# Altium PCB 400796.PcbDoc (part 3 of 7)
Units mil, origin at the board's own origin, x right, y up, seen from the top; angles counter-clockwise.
Board outline 2086.61 x 2086.61 mil, 6 copper layers (Top Layer, Mid Layer 1, Mid Layer 2, Mid Layer 3, Mid Layer 4, Bottom Layer), stack 58.818 mil thick; 313 components, 234 nets, 1244 pads, 2538 vias.
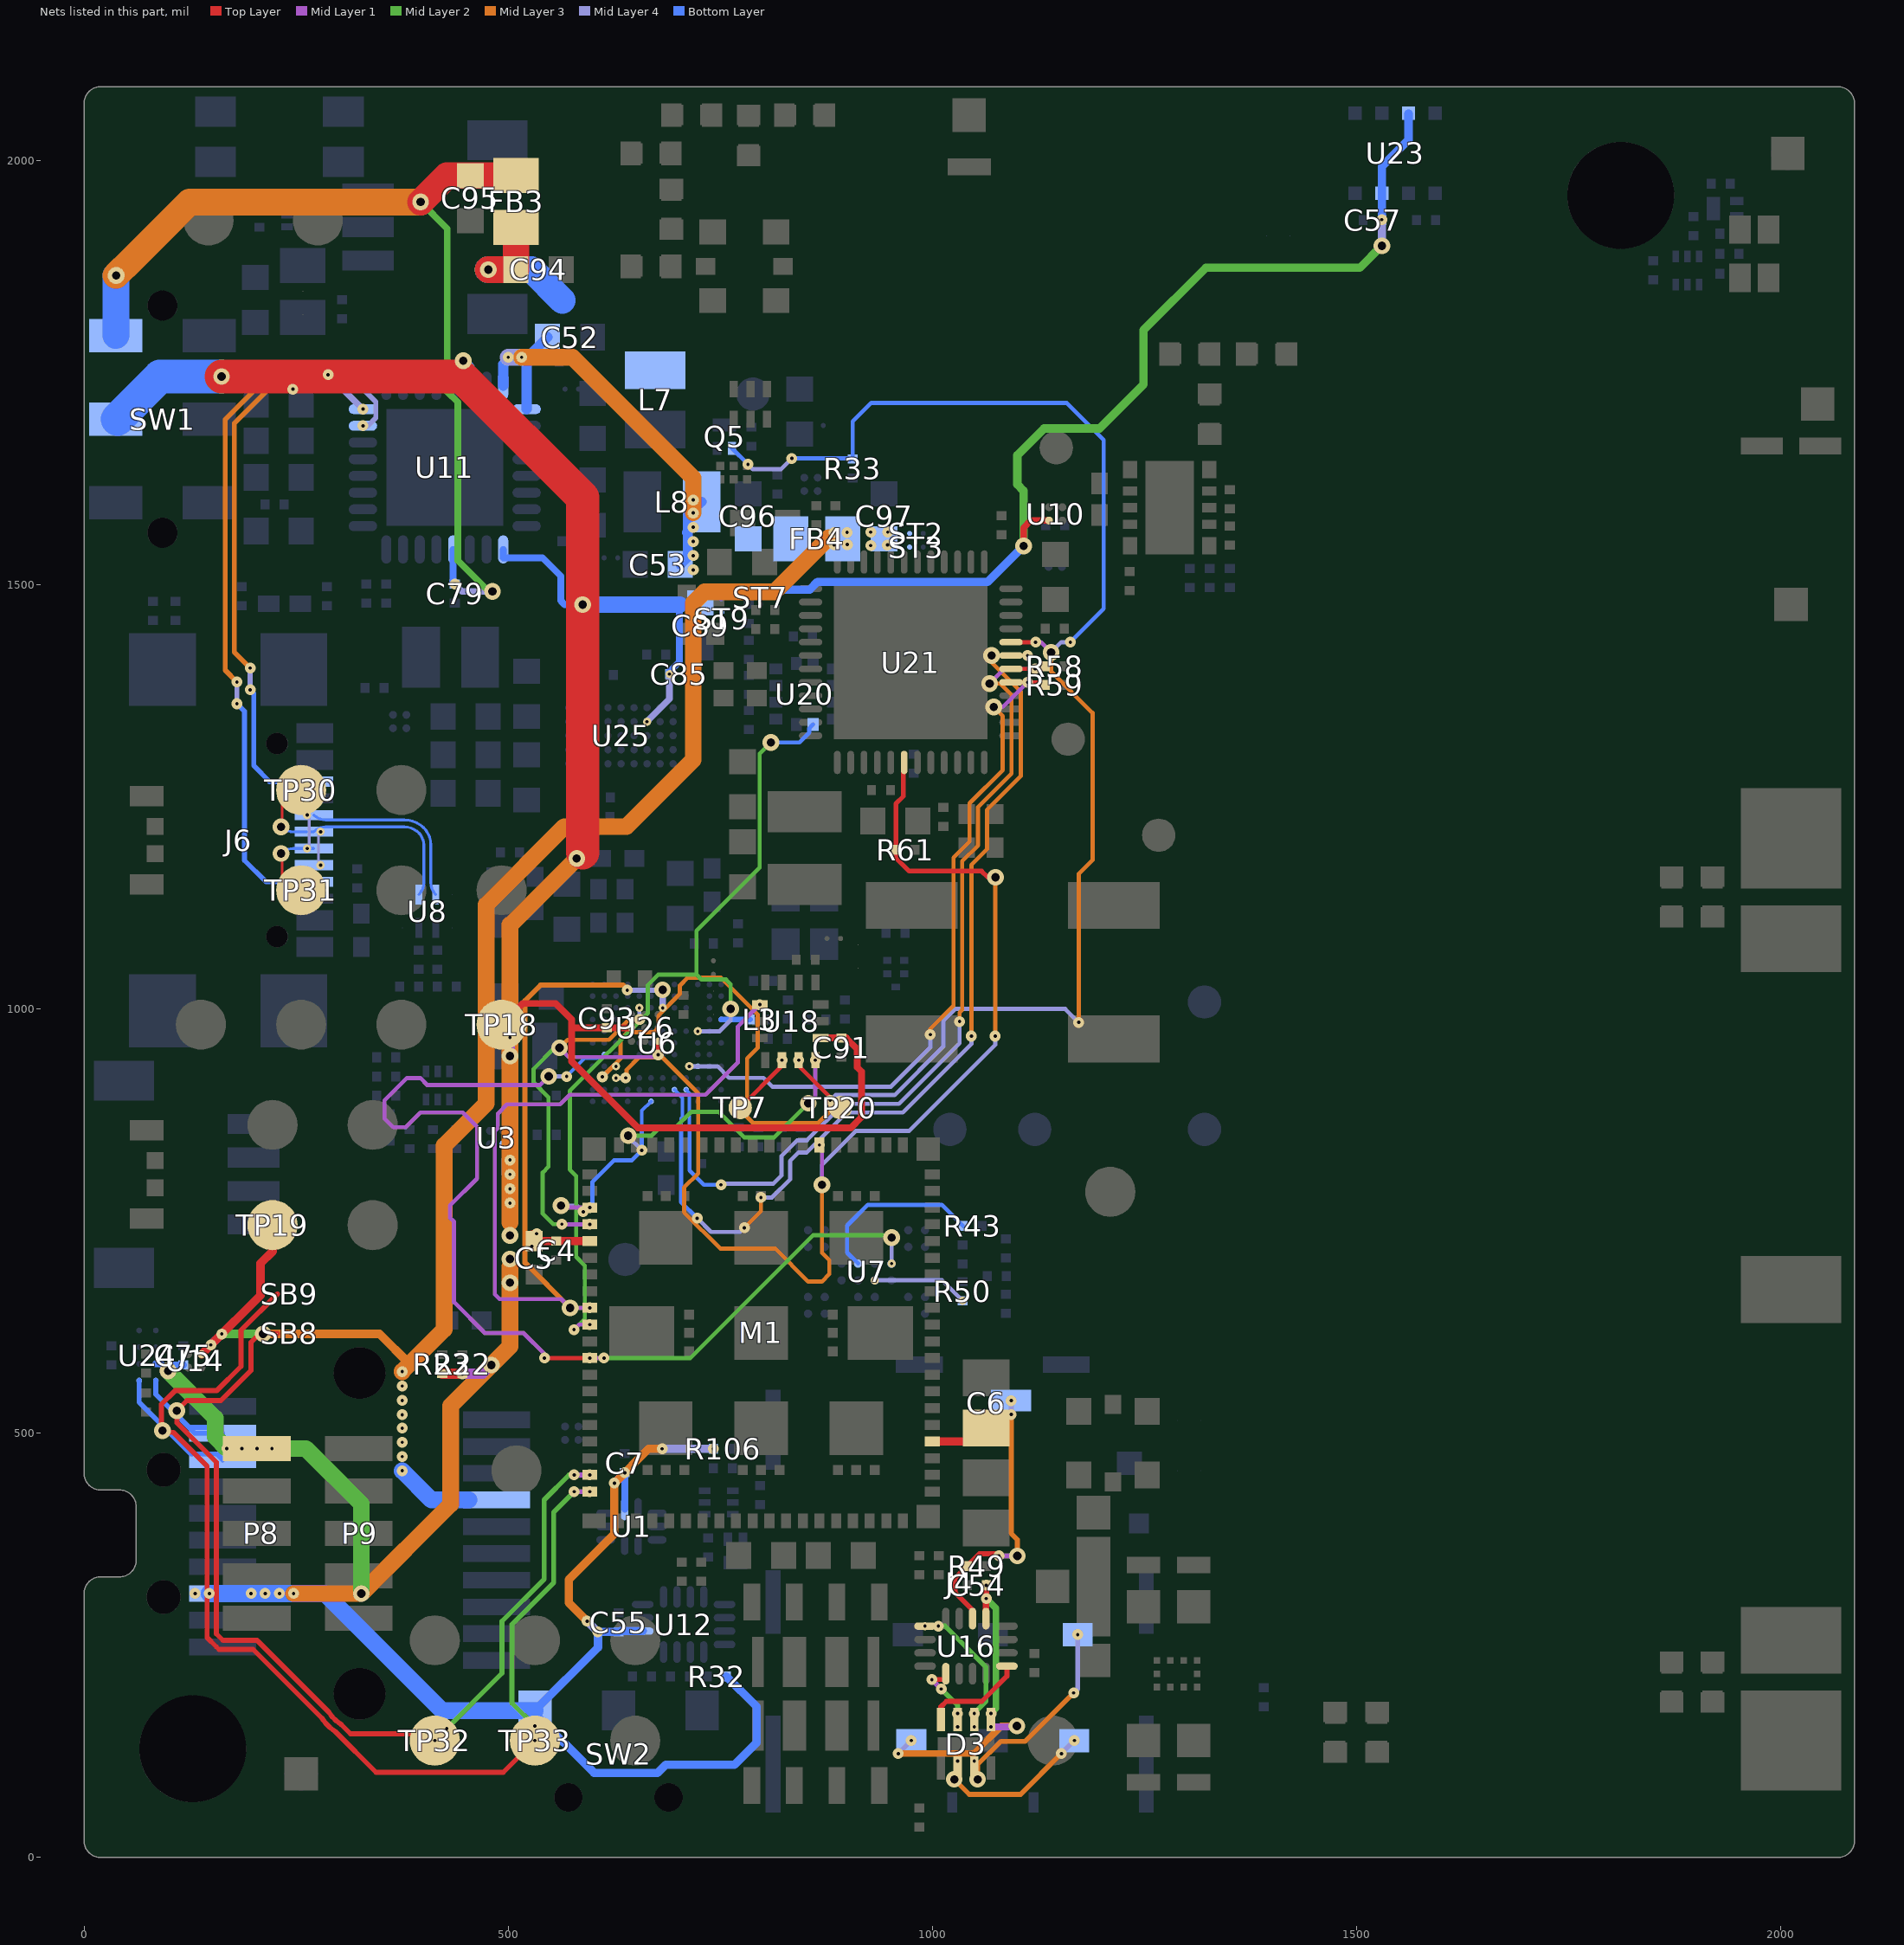
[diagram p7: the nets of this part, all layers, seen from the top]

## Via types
v1: diameter 12.8, hole 3.94, Mid Layer 4 to Bottom Layer, tented both sides, 653 vias
v2: diameter 12.8, hole 3.94, Top Layer to Mid Layer 1, tented both sides, 560 vias
v3: diameter 12.8, hole 3.94, Mid Layer 3 to Mid Layer 4, tented both sides, 388 vias
v4: diameter 19.68, hole 9.84, Mid Layer 1 to Mid Layer 4, tented both sides, 311 vias
v5: diameter 12.8, hole 3.94, Mid Layer 1 to Mid Layer 2, tented both sides, 265 vias
v6: diameter 19.68, hole 9.84, Top Layer to Bottom Layer, tented both sides, 169 vias
v7: diameter 9.84, hole 3.94, Mid Layer 4 to Bottom Layer, tented both sides, 105 vias
v8: diameter 12.8, hole 3.94, Top Layer to Mid Layer 1, tented top, 70 vias
v9: diameter 9.84, hole 3.94, Top Layer to Mid Layer 1, tented both sides, 17 vias

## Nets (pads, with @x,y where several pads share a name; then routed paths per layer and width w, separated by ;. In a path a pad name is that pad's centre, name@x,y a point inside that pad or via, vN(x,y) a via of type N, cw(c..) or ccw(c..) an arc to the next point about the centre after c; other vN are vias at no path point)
1V8: C79.1 C95.2 FB3.2 SW1.3 U11.12 | length 1176.4
  Top Layer w31.5: v6(396.65,1950.79) 427.79,1981.93 FB3.2@509.1,1981.93
  Mid Layer 2 w7.87: v6(396.65,1950.79) 428.15,1919.29 428.15,1727.2 440.63,1714.71 440.63,1528.2 476.88,1491.95 v4(481.32,1491.95)
  Mid Layer 3 w31.5: v6(37.8,1864.21) 56.6,1883 124.38,1950.79 v6(396.65,1950.79)
  Mid Layer 4 w7.87: v1(437.01,1500.39) 445.45,1491.95 v4(481.32,1491.95)
  Bottom Layer w7.87: C79.1@435.04,1500.39 U11.12@435.04,1541.34
  Bottom Layer w31.5: SW1.3@37.4,1793.31 37.8,1793.7 v6(37.8,1864.21)
1V8_IND: C52.2 C94.2 FB3.1 L7.1 U11.1 | length 279.9
  Top Layer w31.5: v6(476.38,1871.06) C94.2@509.1,1871.06 FB3.1@509.1,1920.9
  Bottom Layer w11.81: U11.1@521.65,1706.69 521.65,1766.89 C52.2@546.26,1791.5
  Bottom Layer w31.5: v6(476.38,1871.06) 527.56,1871.06 563.71,1834.92
1V8_SW: C4.1 C5.1 C7.1 C55.1 C57.2 C75.2 C85.1 C89.2 C91.2 C93.2 M1.65 P8.1 P9.3 R22.1 R23.1 R32.1 R106.1 ST7.1 ST9.1 SW1.2 SW2.3 TP18.1 U1.1 U3.A2 U10.A2 U11.9 U11.30 U12.14 U18.5 U23.2 U23.6 U24.C1 U25.C4 U26.B3 | length 6568.8
  Top Layer w7.87: v6(1107.28,1545.28) 1107.28,1566.95 1115.73,1575.39 U10.A2@1137.32,1575.39
  Top Layer w8: TP18.1@492.13,981.39 517.14,1006.4 555.8,1006.4 574.65,987.55 574.65,977.75 ; C5.1@527.54,735.1 v2(533.52,735.1) ; C5.1@530.62,726.38 C5.1@530.62,729.24 ; U26.B3@645.2,977.61 C93.2@616.14,977.61 574.79,977.61 574.65,977.75 ; U18.5@868.33,965.69 C91.2@892.87,965.69 898.4,965.69 911.14,952.95 911.14,931.27 916.27,926.15 916.27,872.24 903.87,859.84 652.83,859.84 574.65,938.02 574.65,977.75
  Top Layer w9.84: C5.1@530.62,726.38 M1.65@596.16,726.38
  Top Layer w12: R23.1@422.16,570.07 v2(445.78,570.07) ; TP18.1@492.13,981.39 501.95,971.56 v2(501.95,966.21)
  Top Layer w39.37: v6(162.13,1745.08) 444.88,1745.08 587.6,1602.36 v6(587.6,1476.38) v6@587.6,1184.05
  Mid Layer 1 w12: v2(445.78,570.07) 469.78,570.07 v4(480.05,580.34) ; v4(501.95,944.46) v2(501.95,966.21)
  Mid Layer 2 w9.84: v6(1107.28,1545.28) 1107.28,1610.53 1099.95,1617.87 1099.95,1652.43 1131.39,1683.87 1196.85,1683.87 1248.57,1735.59 1248.57,1799.65 1322.27,1873.35 1503.71,1873.35 v4(1529.53,1899.17)
  Mid Layer 2 w19.68: v6(99.15,573.25) 154.61,517.79 154.61,495.58 v5(168.31,481.89) v5(186.02,481.89) 261.65,481.89 326.77,416.77 v4(326.77,311.02)
  Mid Layer 3 w9.84: v3(592.97,278.54) 571.51,300 571.51,327.6 625.06,381.14 v3(625.06,441.2) 665.52,481.66 v3(681.37,481.66)
  Mid Layer 3 w19.68: v3(247.05,311.02) v4(326.77,311.02) 432.09,416.34 432.09,532.38 v4(480.05,580.34) 501.97,602.26 v4(501.97,677.25) v4@501.97,696.25 ; 501.95,748.03 501.95,1099.41 ; 502.95,1099.41 v6(580.71,1177.16)
  Mid Layer 4 w7.87: v7@663.58,1338.92 690.02,1365.36 v7(690.02,1394.5)
  Mid Layer 4 w9.84: v3(592.97,278.54) v1(605.76,265.75) ; v3(625.06,441.2) v1(637.25,453.39) ; v3(681.37,481.66) 681.45,481.59 v1(741.84,481.59) ; v4(1529.53,1899.17) v1(1529.53,1929.98)
  Bottom Layer w7.87: U11.9@494.09,1541.34 494.09,1531.5 540.35,1531.5 562.01,1509.84 562.01,1481.3 ; 562.4,1480.41 566.43,1476.38 v6(587.6,1476.38) ; v7(690.02,1394.5) 690.02,1397.7 701.77,1409.45 701.77,1476.38
  Bottom Layer w8: U24.C1@84.65,581.69 90.71,581.69 v6(99.15,573.25) 106.21,580.31 C75.2@117.13,580.31 ; U1.1@637.25,410.44 v1(637.25,453.39)
  Bottom Layer w9.84: C55.1@629.92,265.75 v1(605.76,265.75) 605.76,247.49 SW2.3@531.5,173.23 531.5,169.23 600.98,99.75 675.98,99.75 685.5,109.27 766.56,109.27 792.81,135.52 792.81,177.62 R32.1@756.97,213.46 ; C55.1@631.89,266.73 U12.14@658.46,266.73 ; 750.92,1485.58 759.41,1494.07 855.44,1494.07 864.5,1503.13 1065.14,1503.13 v6(1107.28,1545.28) ; v1(1529.53,1929.98) U23.6@1529.53,1961.08 1529.53,1992.45 1561.02,2023.95 U23.2@1561.02,2054.93
  Bottom Layer w11.81: v6(446.85,1763.78) 454.72,1755.9 U11.30@454.72,1734.25
  Bottom Layer w19.68: v1@501.97,805.12 v1(501.97,821.85) ; v6@588.58,1476.38 701.77,1476.38
  Bottom Layer w20: v1(147.64,311.02) P9.3@163.39,311.02 284.06,311.02 421.85,173.23 SW2.3@531.5,173.23
  Bottom Layer w39.37: SW1.2@39.37,1694.88 89.57,1745.08 v6(162.13,1745.08)
  other v1: 130.9,311.02 501.97,771.06 501.97,787.99 501.97,804.92
  other v2: 203.74,481.89 221.46,481.89 527.6,720.22
  other v3: 196.85,311.02 213.58,311.02 230.32,311.02
  other v4: 501.97,705.18 501.97,733.11
  other v7: 663.58,1338.39
2.4G_SW_CTRL: Q5.1 R33.2 U6.H10 U21.44 | length 2225.4
  Top Layer w4.92: U21.44@1092.52,1432.09 v2(1121.53,1432.09)
  Mid Layer 1 w4.92: v2(1121.53,1432.09) 1127.76,1432.09 v4(1139.76,1420.09)
  Mid Layer 3 w4.92: v3(610.91,919.91) 632.23,941.23 632.23,964.39 640.23,972.39 671.17,972.39 676.89,978.11 676.89,992.1 702.19,1017.4 702.19,1027.49 711.46,1036.76 750.52,1036.76 793.86,993.42 793.86,953.82 781.5,941.47 781.5,872.48 788.65,865.34 865.19,865.34 879.41,879.55 v3(879.41,892.35) ; v4(1139.76,1420.09) 1139.76,1397.47 1188.57,1348.66 1188.57,1175.36 1172.28,1159.08 v3(1172.28,984.03)
  Mid Layer 4 w4.92: v3(610.91,919.91) 623.28,932.28 v7(626.95,932.28) ; v1(782.48,1641.73) 788.39,1635.83 821.48,1635.83 v1(834.22,1648.57) ; v3(879.41,892.35) 885.44,898.38 955.44,898.38 1012.78,955.72 1012.78,985.91 1026.71,999.84 1156.47,999.84 v3(1172.28,984.03) ; v4(1139.76,1420.09) 1151.76,1432.09 v1(1162.4,1432.09)
  Bottom Layer w4.92: Q5.1@763.78,1660.43 v1(782.48,1641.73) ; v1(834.22,1648.57) 900.96,1648.57 R33.2@902.93,1646.6 ; R33.2@905.94,1647.97 905.94,1692.1 927.92,1714.07 1157.97,1714.07 1201.77,1670.28 1201.77,1583.66 1201.77,1471.46 v1(1162.4,1432.09)
3V3: C97.2 FB4.2 P9.14 ST2.1 ST3.1 TP19.1 U14.A2 | length 1817.2
  Top Layer w10: U14.A2@138.56,593.09 v2(149.47,604) 207.97,662.5 207.97,699.98 222.15,714.16 TP19.1@222.15,745.17
  Mid Layer 1 w10: v2(149.47,604) v5(162.41,616.94)
  Mid Layer 2 w10: v5(162.41,616.94) v4(211.05,616.94)
  Mid Layer 3 w10: v4(211.05,616.94) 348.35,616.94 383.73,581.56
  Mid Layer 3 w19.68: v3(375,572.45) 375,572.83 383.73,581.56 424.59,622.42 424.59,838.96 473.9,888.27 473.9,1122.52 566.07,1214.69 639.24,1214.69 717.97,1293.43 717.97,1478.04 731.33,1491.4 813.98,1491.4 877.66,1555.08 878.77,1555.08
  Bottom Layer w19.68: v1(375,455.71) 409.45,421.26 P9.14@453.74,421.26
  other v1: 375,472.44 375,489.18 375,505.91 927.21,1545.87 946.89,1546.67 927.21,1561.69 947.18,1561.8
  other v3: 375,521.66 375,538.59 375,555.52 883.96,1546.84 899.55,1547.07 883.77,1561.08 899.32,1561.46
3V3_IND: C53.2 C96.2 FB4.1 L8.1 U11.32 | length 464
  Mid Layer 3 w19.68: v3(515.75,1767.72) 575.79,1767.72 717.97,1625.53 v3(717.97,1599.64) v3(717.97,1584.39)
  Mid Layer 4 w19.68: v1(500,1767.72) v3(515.75,1767.72)
  Bottom Layer w11.81: U11.32@494.09,1734.25 494.09,1759.68 500,1765.59 v1(500,1767.72) ; C53.2@702.76,1523.62 711.61,1532.48 L8.1@711.61,1581.3 ; 710.63,1561.02 L8.1@711.42,1561.81 ; 711.42,1556.64 L8.1@711.42,1561.81 ; L8.1@727.76,1597.44 L8.1@711.61,1581.3 ; L8.1@711.42,1561.81 711.42,1567.46 711.42,1581.1 L8.1@711.61,1581.3
  other v1: 717.97,1517.26 717.97,1534 717.97,1550.73 717.97,1567.46
4FF_1V8: C54.1 D3.5 J4.C1 U16.1 | length 418.4
  Top Layer w7.87: U16.1@1062.99,281.5 C54.1@1062.99,320.47
  Mid Layer 1 w5.91: v5(1063.38,305.12) v2(1063.38,320.87)
  Mid Layer 1 w7.87: v5(1068.9,169.68) v9(1068.9,153.94) v4@1099.41,153.94
  Mid Layer 2 w7.87: v5(1063.38,305.12) 1074.8,293.7 1074.8,175.59 v5(1068.9,169.68)
  Mid Layer 3 w7.87: v3(959.69,122.48) 1048.66,122.48 1081.1,154.92 v4(1099.41,154.92)
  Mid Layer 4 w5.91: v3(959.69,122.48) v1(975,137.8)
4FF_CLK: D3.7 U16.9 | length 90.9
  Top Layer w5.91: v2(999.19,209.65) 999.24,209.7 1014.47,209.7 1015.75,210.97 U16.9@1015.75,216.54
  Mid Layer 1 w5.91: v2(999.19,209.65) v5(1010.33,198.51) ; v9(1029.53,153.94) v5(1029.53,169.68)
  Mid Layer 2 w5.91: v5(1010.33,198.51) 1029.53,179.31 v5(1029.53,169.68)
4FF_DETECT: J4.DSW R49.1 U16.2 | length 325
  Top Layer w5.91: R49.1@1037.99,340.55 1026.67,329.23 1026.67,312.04 1045.87,292.85 1045.87,292.08 1047.24,290.71 U16.2@1047.24,281.5 ; R49.1@1040.95,343.5 1055.27,357.83 1077.14,357.83 1078.29,356.68 v2(1078.29,355.43)
  Mid Layer 1 w5.91: v2(1078.29,355.43) v4(1100.03,355.43)
  Mid Layer 3 w5.91: v3(1092.72,521.98) 1092.72,381.75 1100.03,374.44 v4(1100.03,355.43)
  Mid Layer 4 w5.91: v3(1092.72,521.98) v1(1092.72,538.39)
4FF_IO: D3.6 U16.5 | length 168
  Mid Layer 1 w5.91: v9(991.14,272.64) v5(1006.89,272.64) ; v9(1049.21,153.94) v5(1049.21,169.68)
  Mid Layer 2 w5.91: v5(1006.89,272.64) 1014.76,272.64 1062.99,224.41 1062.99,183.96 1049.21,170.18 v5(1049.21,169.68)
4FF_RST: D3.8 U16.13 | length 128.1
  Top Layer w5.91: D3.8@1009.84,153.94 D3.8@1009.84,162.4 1009.84,177.56 1016.34,184.06 1058.07,184.06 1087.6,213.58 U16.13@1087.6,225.39
ADXL367_INT: M1.70 U6.E3 U20.5 | length 1043.2
  Mid Layer 1 w4.92: v5(577.46,621.95) 583.46,627.95 v2(595.98,627.95)
  Mid Layer 2 w4.92: v5(577.46,621.95) 590.32,634.81 590.32,697.43 579.99,707.75 579.99,803.09 572.6,810.48 572.6,903.13 664.32,994.85 664.32,1027.9 676.77,1040.35 721.81,1040.35 ; v4(762.17,1000) 762.17,1028.98 756.63,1034.51 727.65,1034.51 721.81,1040.35 ; v6(809.51,1313.98) 796.26,1300.73 796.26,1166.34 721.81,1091.89 721.81,1040.35
  Mid Layer 4 w4.92: v7(723.41,973.62) 749.07,973.62 762.17,986.72 v4(762.17,1000)
  Bottom Layer w4.92: v6(809.51,1313.98) 842.98,1313.98 854.76,1325.76 854.76,1330.75 U20.5@859.25,1335.24
ANT: L3.2 U6.D1 | length 34.1
  Bottom Layer w6.5: U6.D1@750.97,987.4 L3.2@785.02,987.4
ASCL: TP20.1 U18.3 | length 76.4
  Top Layer w4.92: v2(842.25,939.61) 842.25,932.82 TP20.1@891.46,883.61
ASDA: TP7.1 U18.2 | length 76.4
  Top Layer w4.92: TP7.1@773.35,883.61 822.56,932.82 v2(822.56,939.61)
BMI270_CS: M1.69 U6.C6 U18.12 | length 1289.3
  Mid Layer 1 w4.92: v2(595.98,647.64) 573.09,647.64 v4(572.97,647.52) 562.41,658.08 489.63,658.08 484.15,663.56 484.15,855.82 487.66,859.33 487.66,876.48 498.65,887.47 518.63,887.47 557,887.47 561.26,887.47 572.6,898.82 732.6,898.82 770.37,936.59 770.37,978.96 v2(796.48,1005.06)
  Mid Layer 2 w8: v4@675.88,1022.48 v4@676.88,1022.48
  Mid Layer 3 w6: v4(572.97,647.52) 519.74,700.76 519.74,1009.68 537.93,1027.87 635.39,1027.87 636.19,1027.07
  Mid Layer 4 w6: v3(640.19,1022.07) 676.47,1022.07 v4@676.88,1022.48
  Mid Layer 4 w8: v4@676.38,1021.98 682.07,1016.29 v7(682.07,1001.18)
  other v4: 681.88,1022.48
BMI270_INT: M1.63 U6.L7 U18.4 | length 568.6
  Mid Layer 1 w4.92: v4(562.34,768.07) 564.66,765.75 v2(595.98,765.75) ; v4(853.58,888.79) 861.93,897.14 v2(861.93,939.61)
  Mid Layer 2 w4.92: v4(641.39,850.55) 668.91,850.55 677.73,859.36 696.52,859.36 715.93,878.77 747.8,878.77 777.98,848.59 813.39,848.59 v4(853.58,888.79)
  Mid Layer 4 w4.92: v4(562.34,768.07) 581.18,768.07 v1(588.3,760.95) ; v4(641.39,850.55) 641.39,849.26 v1(657.39,833.26)
  Bottom Layer w4.13: 657.39,860.55 657.39,880.05 U6.L7@668.29,890.95
  Bottom Layer w4.92: v1(588.3,760.95) 599.05,771.7 599.05,795.84 624.82,821.61 645.74,821.61 v1(657.39,833.26) 657.39,859
BMM350_INT: M1.64 U6.C8 U26.A1 | length 542.1
  Top Layer w4.92: v2(676.7,945.86) U26.A1@676.7,961.86
  Mid Layer 1 w4.92: v4(560.43,954.09) 571.3,943.22 674.06,943.22 v2(676.7,945.86) ; v5(563.17,746.28) 563.38,746.06 v2(595.98,746.06)
  Mid Layer 2 w4.92: v4(560.43,954.09) 554.57,954.09 529.92,929.44 529.92,913.31 547.37,895.86 547.37,813.94 540.62,807.19 540.62,758.55 552.9,746.28 v5(563.17,746.28)
  Mid Layer 3 w4.92: v4(560.43,954.09) 569.89,963.55 618.73,963.55 642.46,987.28 v3(654.75,987.28)
  Mid Layer 4 w4.92: v7(654.51,1001.18) 654.51,987.52 v3(654.75,987.28)
BUCKEN: M1.47 R61.1 U6.J10 U21.30 | length 1360.6
  Top Layer w5.51: U21.30@966.54,1290.35 966.08,1289.9 966.08,1278.39 965.79,1278.09 965.79,1250.65 956.77,1241.63 R61.1@956.77,1187.3 956.77,1178.07 972.44,1162.4 1057.84,1162.4 v6@1065.17,1155.07
  Mid Layer 1 w4.92: v2(866.65,839.57) 869.65,836.57 v4(869.65,792.57)
  Mid Layer 3 w4.92: v3@639.3,919.6 639.3,928 654.18,942.88 681.49,942.88 723.85,900.52 723.85,806.06 707.19,789.4 707.19,760.16 749.8,717.55 814.73,717.55 853.61,678.67 869.6,678.67 878.36,687.43 878.36,703.75 869.65,712.46 v4(869.65,792.57) ; v3(1073.82,967.86) 1073.82,1154.72 v6(1074.17,1155.07)
  Mid Layer 4 w4.92: v7(626.95,918.5) 638.2,918.5 v3@639.3,919.6 ; v4(869.65,792.57) 869.65,816.19 909.52,856.06 972.4,856.06 1073.82,957.47 v3(1073.82,967.86)
  other v3: 638.3,918.6
CC1: J6.A5 U11.23 | length 872
  Mid Layer 3 w5.91: 166.33,1494.01 166.33,1541.42 ; 166.34,1494 166.34,1398.97 v3(180.16,1385.14) ; 166.34,1541.43 166.34,1694.53 218.98,1747.17 v3(287.74,1747.17)
  Mid Layer 4 w5.91: v1(180.16,1359.55) v3(180.16,1385.14) ; v3(287.74,1747.17) 312.07,1747.17 343.99,1715.26 343.99,1696.27 334.73,1687.01 v1(328.74,1687.01)
  Bottom Layer w5.91: v1(180.16,1359.55) 189.17,1350.54 189.17,1175 214.57,1149.61 J6.A5@270.87,1149.61
CC2: J6.B5 U11.24 | length 669.6
  Mid Layer 3 w5.91: v3(195.87,1401.57) 177.17,1420.28 177.17,1493.72 177.17,1498.49 177.16,1536.94 177.17,1634.14 177.17,1690.05 217.34,1730.22 v3(246.21,1730.22)
  Mid Layer 4 w5.91: v1(195.87,1375.98) v3(195.87,1401.57)
  Mid Layer 4 w7.87: v3(246.21,1730.22) 305.21,1730.22 v1(328.74,1706.69)
  Bottom Layer w5.91: v1(195.87,1375.98) 200,1371.85 200,1286.48 218.77,1267.72 J6.B5@270.87,1267.72
CLK: D3.2 J4.C3 | length 191.1
  Mid Layer 1 w5.91: v4@1029.53,99.79 v9(1029.53,113.78) v9@1029.53,115.75
  Mid Layer 3 w5.91: v4(1025.59,92.13) 1043.31,74.41 1103.74,74.41 v3(1151.81,122.48)
  Mid Layer 4 w5.91: v3(1151.81,122.48) v1(1167.13,137.8)
COEX_GRANT: U6.K5 U21.43 | length 1165.6
  Top Layer w4.92: U21.43@1092.52,1416.34 v2(1111.92,1416.34)
  Mid Layer 1 w4.92: v4(1069.54,1416.34) v2(1111.92,1416.34)
  Mid Layer 3 w4.92: v3(778.34,742.09) 797.83,761.58 v3(797.83,777.68) ; v3(1045.75,967.86) 1045.75,1169.44 1064.15,1187.84 1064.15,1234.28 1103.99,1274.13 1103.99,1373.92 1069.54,1408.37 v4(1069.54,1416.34)
  Mid Layer 4 w4.92: v1(722.67,753.31) 738.9,737.09 773.34,737.09 v3(778.34,742.09) ; v3(797.83,777.68) 810.82,777.68 832.14,799 832.14,820.64 842.21,830.71 851.83,830.71 898.94,877.82 965.08,877.82 1045.75,958.49 v3(1045.75,967.86)
  Bottom Layer w4.13: U6.K5@695.85,904.72 705.38,895.2 705.38,872.86 703.64,871.12 703.64,859
  Bottom Layer w4.92: 703.64,859 703.64,772.35 v1(722.67,753.31)
COEX_REQ: R58.1 U6.K4 U21.42 | length 1074.2
  Top Layer w4.92: U21.42@1092.52,1400.59 v2(1120.92,1400.59) 1130.04,1400.59 R58.1@1132.99,1403.54
  Mid Layer 1 w4.92: v4(1067.29,1383.25) 1084.64,1400.59 v2(1120.92,1400.59)
  Mid Layer 3 w4.92: v3(1031.95,985.15) 1031.95,995.68 1034.95,998.68 1034.95,1173.95 1053.66,1192.66 1053.66,1237.94 1093,1277.28 1093,1369.96 1079.71,1383.25 v4(1067.29,1383.25)
  Mid Layer 4 w4.92: v1(750.73,792.74) 751.82,793.83 812.25,793.83 821.93,803.51 821.93,826.55 840.46,845.08 852,845.08 895.01,888.09 960.54,888.09 1031.95,959.5 v3(1031.95,985.15)
  Bottom Layer w4.13: U6.K4@709.63,904.72 713.59,900.76 713.59,859
  Bottom Layer w4.92: 713.59,859 713.59,809.58 730.43,792.74 v1(750.73,792.74)
COEX_STATUS: R59.1 U6.H3 U21.41 | length 857.7
  Top Layer w4.92: U21.41@1092.52,1384.84 v2(1111.92,1384.84) 1130.04,1384.84 R59.1@1132.99,1381.89
  Mid Layer 1 w4.92: v4(1072.09,1355.7) 1082.78,1355.7 v2(1111.92,1384.84)
  Mid Layer 3 w4.92: v3(997.4,969.64) 997.4,976.36 1024.68,1003.64 1024.68,1178.13 1043.65,1197.1 1043.65,1242.24 1082.79,1281.38 1082.79,1345 v4(1072.09,1355.7)
  Mid Layer 4 w4.92: v7(713.41,932.28) 746.64,932.28 760.29,918.63 800.81,918.63 811.21,908.23 951.06,908.23 997.4,954.58 v3(997.4,969.64)
  Bottom Layer w4.92: v7(713.41,932.28) U6.H3@723.41,932.28
D:J6_N: J6.A7 J6.B7 TP30.1 U8.2 | length 323.3
  Top Layer w3.27: v6(232.28,1214.57) 233.44,1215.73 TP30.1@233.44,1255.1
  Mid Layer 4 w3.27: v7@276.3,1169.29 v7@276.3,1208.66
  Bottom Layer w3.27: v6(232.28,1214.57) ccw(c246.54,1228.82) 246.54,1208.66 J6.A7@270.87,1208.66 cw(c284.64,1194.89) 284.64,1214.37 377.5,1214.37 cw(c377.5,1190.11) 394.65,1207.26 cw(c380.62,1193.24) 400.46,1193.24 400.46,1148.55 cw(c380.98,1148.55) U8.2@394.75,1134.77
  other v7: 278.74,1169.29 278.74,1208.66
D:J6_P: J6.A6 J6.B6 TP31.1 U8.3 | length 336.3
  Top Layer w3.27: v6(232.28,1183.07) 233.44,1181.91 TP31.1@233.44,1142.54
  Mid Layer 4 w3.27: v7@265.43,1188.98 v7@265.43,1228.35
  Bottom Layer w3.27: v6(232.28,1183.07) cw(c246.54,1168.81) 246.54,1188.98 J6.A6@270.87,1188.98 ; J6.B6@270.87,1228.35 ccw(c284.64,1242.12) 284.64,1222.64 377.59,1222.64 cw(c377.59,1190.34) 400.43,1213.18 400.56,1213.06 cw(c380.81,1193.32) 408.73,1193.32 408.73,1148.55 ccw(c428.21,1148.55) U8.3@414.44,1134.77
  other v7: 262.99,1188.98 262.99,1228.35
DATA: D3.3 J4.C7 | length 252.1
  Mid Layer 1 w5.91: v4@1049.21,99.79 v9(1049.21,113.78) v9@1049.21,115.75
  Mid Layer 3 w5.91: v4(1053.15,92.13) 1053.15,109.44 1080.46,136.76 1109.2,136.76 v3(1166.34,193.9)
  Mid Layer 4 w5.91: v3(1166.34,193.9) 1171.06,198.62 v1(1171.06,262.6)
DEC0: C6.1 M1.24 | length 70.1
  Top Layer w10: M1.24@999.7,490.16 1047.46,490.16 C6.1@1063.24,505.94
EXP_BOARD.PIN1: M1.80 P9.8 SB9.1 TP33.1 U24.D2 | length 1489.6
  Top Layer w5.91: v6(92.52,502.95) 91.33,504.14 91.33,534.2 107.18,550.04 156.33,550.04 185.14,578.85 185.14,621.24 SB9.1@228.13,664.23 ; v6@94.43,501.04 105.24,501.04 145.08,461.2 145.08,259.18 156.03,248.23 159.18,245.08 199.41,245.08 280.36,164.12 ccw(c324.8,192.91) 295.47,148.83 cw(c292.27,143.87) 296.44,148.05 344.09,100.39 494.09,100.39 v2(531.5,137.8)
  Mid Layer 1 w5.91: v2(531.5,137.8) v5(531.5,154.95) ; v5(577.71,431.1) v2(595.98,431.1)
  Mid Layer 2 w5.91: v5(531.5,154.95) 504.35,182.09 504.35,274.55 553.57,323.76 553.57,406.96 v5(577.71,431.1)
  Bottom Layer w5.91: U24.D2@64.96,562.01 64.96,536.42 125.98,475.39 156.5,475.39 P9.8@163.39,468.5
EXP_BOARD.PIN2: M1.79 P9.9 SB8.1 TP32.1 U24.D1 | length 1351.2
  Top Layer w5.91: v6(109.25,526.57) 121.21,538.54 161.33,538.54 196.65,573.86 196.65,607.1 207.12,617.57 SB8.1@228.13,617.57 ; v6@109.45,526.37 109.45,512.14 155.91,465.69 155.91,263.67 163.67,255.91 203.89,255.91 205.62,254.18 288.39,171.4 288.87,170.92 ccw(c324.8,192.91) 302.81,156.98 303.29,156.5 314.13,145.67 405.51,145.67 v2(413.39,137.8)
  Mid Layer 1 w5.91: v2(413.39,137.8) v5(427.53,151.94) ; v5(577.71,450.79) v2(595.98,450.79)
  Mid Layer 2 w5.91: v5(427.53,151.94) 492.64,217.05 492.64,278.23 542.28,327.88 542.28,421.37 571.7,450.79 v5(577.71,450.79)
  Bottom Layer w5.91: U24.D1@84.65,562.01 84.65,545.76 130.41,500 P9.9@163.39,500 156.5,506.89 124.02,506.89 v6@106.79,524.11
FLASH_C\S\: M1.72 U6.G11 U7.C4 | length 1296.3
  Top Layer w4.92: v2(542.67,588.58) v2(595.98,588.58)
  Mid Layer 1 w4.92: v2(542.67,588.58) 542.67,593.32 517.97,618.02 472.32,618.02 436.04,654.3 436.04,749.31 431.34,754.01 431.34,768.13 463.31,800.11 463.31,860.85 446.28,877.88 396.59,877.88 379.3,860.59 364.46,860.59 354.15,870.9 354.15,891.96 380.65,918.47 396.3,918.47 404.37,910.4 537.61,910.4 v4(547.6,920.39) ; v2(595.98,588.58) v5(612.78,588.58)
  Mid Layer 2 w4.92: v4@547.37,920.61 v4(547.6,920.39)
  Mid Layer 2 w5: v5(612.78,588.58) 714.57,588.58 859.19,733.2 948.97,733.2 v4(951.77,730.4)
  Mid Layer 4 w4.92: v4(547.6,920.39) v1(568.79,920.39)
  Mid Layer 4 w5: v7(951.77,699.8) v4(951.77,730.4)
  Bottom Layer w4.13: v1(568.79,920.39) 590.2,941.79 608.9,941.79 U6.G11@613.17,946.06
FLASH_R\E\S\E\T\: R50.1 U7.D3 | length 113.4
  Mid Layer 4 w4.92: v7(932.09,680.12) 1011.4,680.12 v7(1035.48,656.04)
FLASH_W\P\: R43.1 U7.E4 | length 207.3
  Bottom Layer w4.92: U7.E4@912.4,699.8 899.35,712.85 899.35,744.49 923.98,769.12 1011,769.12 R43.1@1036.02,744.09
